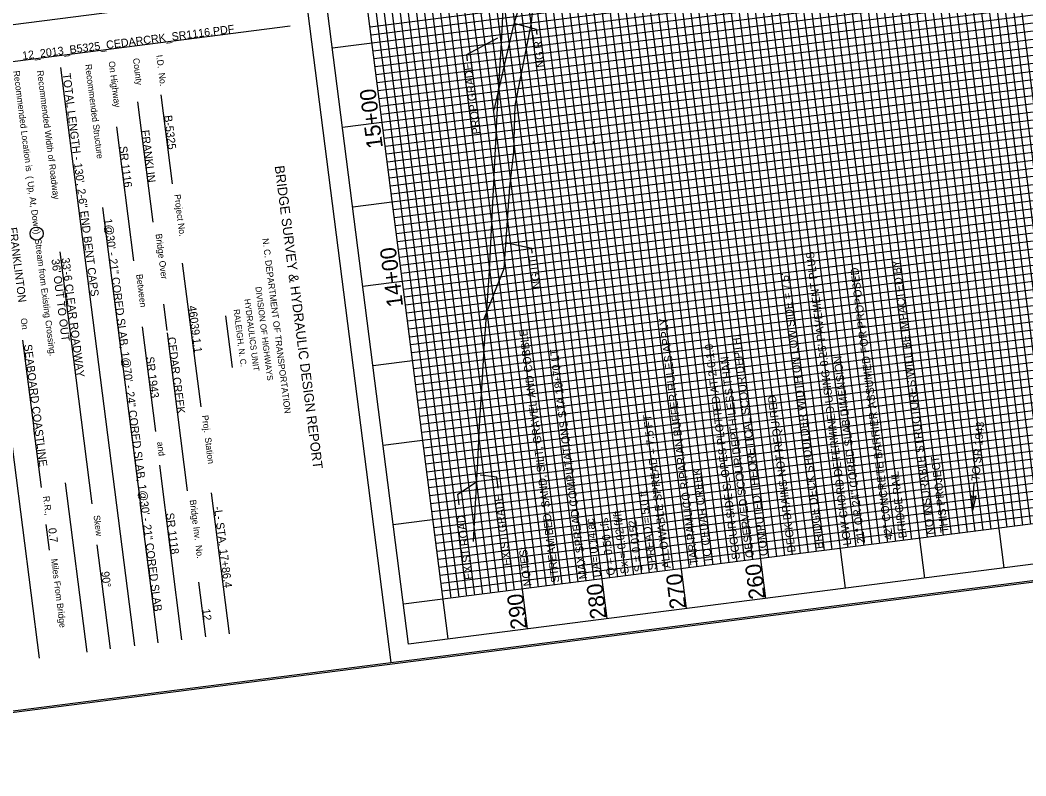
# Model space of a CAD drawing. Extents: x 2166991 to 2168413, y 842679 to 844296.
# Drawn here: x 2167468 to 2168096, y 842679 to 843150 of the extents above; entities that cross this region are included whole.
import ezdxf

# ---------------------------------------------------------------- set-up
doc = ezdxf.new("R2010")
doc.units = 0
for name, color, linetype in [('Exist Horizontal Alignment', 7, 'Continuous'), ('Exist Hydrographic Natural Ground Left', 7, 'Continuous'), ('Exist Hydrographic Natural Ground Right', 7, 'Continuous'), ('Old_Level_46', 7, 'Continuous'), ('Old_Level_61', 7, 'Continuous'), ('Prop Plan Preparation Cover Label', 7, 'Continuous'), ('Prop Plan Preparation Elevation Label', 7, 'Continuous'), ('Prop Plan Preparation Sheet Bridge Report Limited Study CELL', 7, 'Continuous'), ('Prop Plan Preparation Station Label', 7, 'Continuous'), ('Prop Plan Preparation Table Performance Curve CELL', 7, 'Continuous'), ('Scratch_Level_1', 7, 'Continuous'), ('Sheet Plot Border Outside CELL', 7, 'Continuous'), ('Typical Terminator CELL', 7, 'Continuous')]:
    doc.layers.add(name, color=color, linetype=linetype)

msp = doc.modelspace()

# ---------------------------------------------------------------- linework, layer by layer
at = {"layer": 'Exist Horizontal Alignment'}
msp.add_lwpolyline([(2167751.39, 842824.91), (2167752.39, 842844.74), (2167753.95, 842874.72), (2167755.15, 842897.27), (2167757.06, 842927.31), (2167757.92, 842945.41), (2167760.09, 842975.47), (2167761.25, 842993.97), (2167762.76, 843023.98), (2167763.76, 843044.55), (2167765.23, 843074.51), (2167766.29, 843095.78), (2167768.15, 843125.8), (2167769.02, 843139.96), (2167770.48, 843169.95), (2167771.39, 843188.46), (2167770.67, 843218.15), (2167770.25, 843236.07), (2167768.33, 843265.68), (2167767.02, 843285.86), (2167763.97, 843315.19), (2167760.56, 843343.94)], dxfattribs=at)
at = {"layer": 'Exist Hydrographic Natural Ground Left'}
msp.add_lwpolyline([(2167757.79, 842963.56), (2167770.55, 842995.45), (2167773.98, 843046.3), (2167776.61, 843068.3), (2167777.35, 843097.13), (2167787.62, 843148.85), (2167792.18, 843199.84), (2167793.61, 843214.01), (2167797.76, 843250.96), (2167815.06, 843303.58), (2167817.99, 843332.01), (2167815.17, 843366.59)], dxfattribs=at)
at = {"layer": 'Exist Hydrographic Natural Ground Right'}
msp.add_lwpolyline([(2167764.31, 843094.3), (2167776.57, 843147.44), (2167792.18, 843199.84), (2167810.26, 843216.13), (2167772.9, 843247.78)], dxfattribs=at)
at = {"layer": 'Old_Level_46'}
for points in [[(2167791.01, 843141.49), (2167790.62, 843144.55), (2167776.78, 843148.24)], [(2167747.61, 843125.02), (2167747.11, 843128.93), (2167766.47, 843139.45)], [(2167788.04, 843005.03), (2167787.67, 843007.92), (2167771.61, 843011.4)], [(2167742.33, 842847.83), (2167741.48, 842854.49), (2167753.3, 842862.19)], [(2167766.83, 842858.38), (2167765.98, 842865.05), (2167755.49, 842866.42)]]:
    msp.add_lwpolyline(points, dxfattribs=at)
at = {"layer": 'Old_Level_61'}
msp.add_line((2168062.86, 842844.16), (2168064.07, 842861.57), dxfattribs=at)
at = {"layer": 'Prop Plan Preparation Cover Label'}
msp.add_circle((2167478.55, 843017.15), 4.12, dxfattribs=at)
at = {"layer": 'Prop Plan Preparation Sheet Bridge Report Limited Study CELL'}
for p, q in [((2168132.34, 842814.84), (2167973.96, 844054.76)), ((2168082.74, 842808.5), (2167924.37, 844048.43)), ((2168033.15, 842802.17), (2167874.77, 844042.09)), ((2167983.55, 842795.83), (2167825.17, 844035.76)), ((2167933.95, 842789.5), (2167775.57, 844029.42)), ((2168124.21, 842839), (2167972.17, 844029.33)), ((2168134.13, 842840.27), (2167982.09, 844030.6)), ((2167884.35, 842783.16), (2167725.98, 844023.09)), ((2168074.61, 842832.67), (2167922.57, 844023)), ((2168084.53, 842833.93), (2167932.49, 844024.26)), ((2168089.49, 842834.57), (2167937.45, 844024.9)), ((2168094.45, 842835.2), (2167942.41, 844025.53)), ((2168099.41, 842835.83), (2167947.37, 844026.16)), ((2168104.37, 842836.47), (2167952.33, 844026.8)), ((2168109.33, 842837.1), (2167957.29, 844027.43)), ((2168114.29, 842837.73), (2167962.25, 844028.06)), ((2168119.25, 842838.37), (2167967.21, 844028.7)), ((2167834.76, 842776.83), (2167676.38, 844016.75)), ((2168025.02, 842826.33), (2167872.98, 844016.66)), ((2168034.94, 842827.6), (2167882.9, 844017.93)), ((2168039.9, 842828.23), (2167887.86, 844018.56)), ((2168044.86, 842828.87), (2167892.82, 844019.19)), ((2168049.82, 842829.5), (2167897.78, 844019.83)), ((2168054.78, 842830.13), (2167902.74, 844020.46)), ((2168059.74, 842830.77), (2167907.69, 844021.1)), ((2168064.7, 842831.4), (2167912.65, 844021.73)), ((2168069.66, 842832.03), (2167917.61, 844022.36)), ((2167538.09, 844014.21), (2167699.63, 842749.49)), ((2167538.09, 844014.21), (2167699.63, 842749.49)), ((2167785.16, 842770.49), (2167626.78, 844010.42)), ((2167985.34, 842821.26), (2167833.3, 844011.59)), ((2167990.3, 842821.9), (2167838.26, 844012.23)), ((2167995.26, 842822.53), (2167843.22, 844012.86)), ((2168000.22, 842823.16), (2167848.18, 844013.49)), ((2168005.18, 842823.8), (2167853.14, 844014.13)), ((2168010.14, 842824.43), (2167858.1, 844014.76)), ((2168015.1, 842825.06), (2167863.06, 844015.39)), ((2168020.06, 842825.7), (2167868.02, 844016.03)), ((2167935.74, 842814.93), (2167783.7, 844005.26)), ((2167940.7, 842815.56), (2167788.66, 844005.89)), ((2167945.66, 842816.2), (2167793.62, 844006.52)), ((2167950.62, 842816.83), (2167798.58, 844007.16)), ((2167955.58, 842817.46), (2167803.54, 844007.79)), ((2167960.54, 842818.1), (2167808.5, 844008.43)), ((2167965.5, 842818.73), (2167813.46, 844009.06)), ((2167970.46, 842819.36), (2167818.42, 844009.69)), ((2167975.42, 842820), (2167823.38, 844010.33)), ((2167710.76, 842760.99), (2167552.39, 844000.92)), ((2167735.56, 842764.16), (2167577.19, 844004.08)), ((2167886.15, 842808.59), (2167734.11, 843998.92)), ((2167891.11, 842809.23), (2167739.06, 843999.56)), ((2167896.07, 842809.86), (2167744.02, 844000.19)), ((2167901.03, 842810.49), (2167748.98, 844000.82)), ((2167905.98, 842811.13), (2167753.94, 844001.46)), ((2167910.94, 842811.76), (2167758.9, 844002.09)), ((2167915.9, 842812.39), (2167763.86, 844002.72)), ((2167920.86, 842813.03), (2167768.82, 844003.36)), ((2167925.82, 842813.66), (2167773.78, 844003.99)), ((2167836.55, 842802.26), (2167684.51, 843992.59)), ((2167841.51, 842802.89), (2167689.47, 843993.22)), ((2167846.47, 842803.53), (2167694.43, 843993.85)), ((2167851.43, 842804.16), (2167699.39, 843994.49)), ((2167856.39, 842804.79), (2167704.35, 843995.12)), ((2167861.35, 842805.43), (2167709.31, 843995.76)), ((2167866.31, 842806.06), (2167714.27, 843996.39)), ((2167871.27, 842806.69), (2167719.23, 843997.02)), ((2167876.23, 842807.33), (2167724.19, 843997.66)), ((2167786.95, 842795.92), (2167634.91, 843986.25)), ((2167791.91, 842796.56), (2167639.87, 843986.89)), ((2167796.87, 842797.19), (2167644.83, 843987.52)), ((2167801.83, 842797.82), (2167649.79, 843988.15)), ((2167806.79, 842798.46), (2167654.75, 843988.79)), ((2167811.75, 842799.09), (2167659.71, 843989.42)), ((2167816.71, 842799.72), (2167664.67, 843990.05)), ((2167821.67, 842800.36), (2167669.63, 843990.69)), ((2167826.63, 842800.99), (2167674.59, 843991.32)), ((2167737.35, 842789.59), (2167585.31, 843979.92)), ((2167742.31, 842790.22), (2167590.27, 843980.55)), ((2167747.27, 842790.86), (2167595.23, 843981.18)), ((2167752.23, 842791.49), (2167600.19, 843981.82)), ((2167757.19, 842792.12), (2167605.15, 843982.45)), ((2167762.15, 842792.76), (2167610.11, 843983.09)), ((2167767.11, 842793.39), (2167615.07, 843983.72)), ((2167772.07, 842794.02), (2167620.03, 843984.35)), ((2167777.03, 842794.66), (2167624.99, 843984.99)), ((2168182.75, 843209.4), (2167686.78, 843146.05)), ((2168183.39, 843204.44), (2167687.42, 843141.09)), ((2168184.02, 843199.48), (2167663.25, 843132.97)), ((2168184.65, 843194.53), (2167688.68, 843131.17)), ((2168185.29, 843189.57), (2167689.32, 843126.21)), ((2168185.92, 843184.61), (2167689.95, 843121.26)), ((2168186.55, 843179.65), (2167690.58, 843116.3)), ((2167100.22, 843101.38), (2167645.78, 843171.06)), ((2168187.19, 843174.69), (2167691.22, 843111.34)), ((2168187.82, 843169.73), (2167691.85, 843106.38)), ((2168188.45, 843164.77), (2167692.48, 843101.42)), ((2168189.09, 843159.81), (2167693.12, 843096.46)), ((2168189.72, 843154.85), (2167693.75, 843091.5)), ((2167458.71, 843124.09), (2167636.89, 843146.84)), ((2168190.36, 843149.89), (2167669.59, 843083.37)), ((2168190.99, 843144.93), (2167695.02, 843081.58)), ((2168191.62, 843139.97), (2167695.65, 843076.62)), ((2168192.26, 843135.01), (2167696.29, 843071.66)), ((2168192.89, 843130.05), (2167696.92, 843066.7)), ((2168193.52, 843125.09), (2167697.55, 843061.74)), ((2167493.43, 843120.82), (2167539.55, 842759.79)), ((2168194.16, 843120.13), (2167698.19, 843056.78)), ((2168194.79, 843115.17), (2167698.82, 843051.82)), ((2168195.42, 843110.21), (2167699.45, 843046.86)), ((2167556.1, 843103.79), (2167563.18, 843048.33)), ((2168196.69, 843100.29), (2167675.92, 843033.77)), ((2168196.06, 843105.25), (2167700.09, 843041.9)), ((2167541.52, 843099.51), (2167551.12, 843024.38)), ((2168197.32, 843095.33), (2167701.35, 843031.98)), ((2168197.96, 843090.37), (2167701.99, 843027.02)), ((2167528.4, 843083.87), (2167539.08, 843000.26)), ((2168198.59, 843085.41), (2167702.62, 843022.06)), ((2168199.22, 843080.45), (2167703.25, 843017.1)), ((2168199.86, 843075.49), (2167703.89, 843012.14)), ((2168200.49, 843070.53), (2167704.52, 843007.18)), ((2168201.13, 843065.57), (2167705.15, 843002.22)), ((2167440.83, 843059.14), (2167480.03, 842752.21)), ((2168201.76, 843060.61), (2167705.79, 842997.26)), ((2168203.03, 843050.69), (2167682.26, 842984.18)), ((2168202.39, 843055.65), (2167706.42, 842992.3)), ((2168203.66, 843045.73), (2167707.69, 842982.38)), ((2168204.29, 843040.77), (2167708.32, 842977.42)), ((2167519.71, 843033.5), (2167543.21, 842849.5)), ((2168204.93, 843035.81), (2167708.96, 842972.46)), ((2168205.56, 843030.85), (2167709.59, 842967.5)), ((2168206.19, 843025.9), (2167710.22, 842962.54)), ((2168206.83, 843020.94), (2167710.86, 842957.58)), ((2168207.46, 843015.98), (2167711.49, 842952.63)), ((2167493.01, 843005.77), (2167513.09, 842848.51)), ((2168208.09, 843011.02), (2167712.12, 842947.67)), ((2168208.73, 843006.06), (2167712.76, 842942.71)), ((2168209.36, 843001.1), (2167688.59, 842934.58)), ((2167569.51, 842998.77), (2167580.98, 842908.99)), ((2168209.99, 842996.14), (2167714.02, 842932.79)), ((2168210.63, 842991.18), (2167714.66, 842927.83)), ((2168211.26, 842986.22), (2167715.29, 842922.87)), ((2168211.89, 842981.26), (2167715.92, 842917.91)), ((2168212.53, 842976.3), (2167716.56, 842912.95)), ((2167557.66, 842973.2), (2167559.77, 842956.66)), ((2168213.16, 842971.34), (2167717.19, 842907.99)), ((2167596.41, 842965.95), (2167600.55, 842933.52)), ((2167596.41, 842965.95), (2167600.55, 842933.52)), ((2167596.41, 842965.95), (2167600.55, 842933.52)), ((2168213.8, 842966.38), (2167717.82, 842903.03)), ((2167544.34, 842959.06), (2167552.7, 842893.63)), ((2168214.43, 842961.42), (2167718.46, 842898.07)), ((2168215.06, 842956.46), (2167719.09, 842893.11)), ((2167469.79, 842950.77), (2167476.83, 842895.65)), ((2167559.96, 842955.2), (2167572.55, 842856.59)), ((2168215.7, 842951.5), (2167694.93, 842884.98)), ((2168216.33, 842946.54), (2167720.36, 842883.19)), ((2168216.96, 842941.58), (2167720.99, 842878.23)), ((2168217.6, 842936.62), (2167721.63, 842873.27)), ((2168218.23, 842931.66), (2167722.26, 842868.31)), ((2168218.86, 842926.7), (2167722.89, 842863.35)), ((2168219.5, 842921.74), (2167723.53, 842858.39)), ((2168220.13, 842916.78), (2167724.16, 842853.43)), ((2168220.76, 842911.82), (2167724.79, 842848.47)), ((2168221.4, 842906.86), (2167725.43, 842843.51)), ((2168222.03, 842901.9), (2167701.26, 842835.38)), ((2167481.55, 842858.68), (2167476.81, 842895.82)), ((2168222.66, 842896.94), (2167726.69, 842833.59)), ((2168223.3, 842891.98), (2167727.33, 842828.63)), ((2168223.93, 842887.02), (2167727.96, 842823.67)), ((2168224.56, 842882.06), (2167728.59, 842818.71)), ((2168225.2, 842877.1), (2167729.23, 842813.75)), ((2167569.31, 842763.59), (2167555.38, 842872.65)), ((2168225.83, 842872.14), (2167729.86, 842808.79)), ((2167496.3, 842861.59), (2167509.79, 842755.99)), ((2168226.47, 842867.18), (2167730.49, 842803.83)), ((2168227.1, 842862.22), (2167731.13, 842798.87)), ((2167599.07, 842767.39), (2167587.82, 842855.42)), ((2168227.73, 842857.27), (2167731.76, 842793.91)), ((2167554.43, 842761.69), (2167543.24, 842849.25)), ((2168228.37, 842852.31), (2167707.6, 842785.79)), ((2167486.56, 842819.5), (2167484.49, 842835.66)), ((2168231.53, 842827.51), (2167710.76, 842760.99)), ((2167524.67, 842757.89), (2167516.36, 842822.91)), ((2167584.19, 842765.5), (2167579.83, 842799.62))]:
    msp.add_line(p, q, dxfattribs=at)
msp.add_lwpolyline([(2166992.52, 843944.53), (2167154.06, 842679.8), (2168245.2, 842819.17), (2168083.66, 844083.9)], close=True, dxfattribs=at)
at = {"layer": 'Scratch_Level_1'}
msp.add_line((2167826.4, 843073.16), (2167826.21, 843074.63), dxfattribs=at)
at = {"layer": 'Sheet Plot Border Outside CELL'}
msp.add_lwpolyline([(2168246.32, 842818.31), (2168084.52, 844085.01), (2166991.4, 843945.39), (2167153.2, 842678.68)], close=True, dxfattribs=at)
at = {"layer": 'Typical Terminator CELL'}
msp.add_lwpolyline([(2168065.12, 842853.4), (2168062.86, 842844.16), (2168061.85, 842853.68), (2168063.43, 842852.37)], close=True, dxfattribs=at)

# ---------------------------------------------------------------- texts
at = {"layer": 'Old_Level_46'}
for s, p in [('NG RT ', (2167795.88, 843121.2)), ('PROP GRADE', (2167755.75, 843079.52)), ('NG LT', (2167793.31, 842983.17)), ('EXIST GRADE', (2167774.87, 842810.09)), ('EXIST ROAD', (2167750.94, 842801.47))]:
    msp.add_text(s, height=5, rotation=97.27898, dxfattribs=at).set_placement(p)
at = {"layer": 'Old_Level_61'}
msp.add_text('TO SR 1943', height=5, rotation=85.1501, dxfattribs=at).set_placement((2168067.18, 842862.53))
at = {"layer": 'Prop Plan Preparation Cover Label'}
for s, rotation, p in [('12_2013_B5325_CEDARCRK_SR1116.PDF', 7.27898, (2167469.86, 843125.75)), ('TOTAL LENGTH - 130\', 2-6" END BENT CAPS', 277.27898, (2167494.72, 843116.98)), ('B-5325', 277.27898, (2167558.08, 843090.79)), ('FRANKLIN', 277.27898, (2167543.77, 843081.56)), ('SR 1116', 277.27898, (2167530.03, 843071.5)), ('1@30\' - 21" CORED SLAB, 1@70\' - 24" CORED SLAB, 1@30\' - 21" CORED SLAB', 277.27898, (2167520.66, 843026.25)), ('FRANKLINTON', 277.27898, (2167461.25, 843020.77)), ("36' OUT TO OUT", 277.27898, (2167487.76, 843001.01)), ("33'-6 CLEAR ROADWAY ", 277.27898, (2167494.06, 843001.82)), ('46039.1.1', 277.27898, (2167573.26, 842971.95)), ('CEDAR CREEK', 277.27898, (2167560.28, 842952.33)), ('SEABOARD COASTLINE', 277.27898, (2167470.58, 842947.77)), ('SR 1943', 277.27898, (2167546.81, 842940.1)), ('SR 1118', 277.27898, (2167559.27, 842842.57)), ('-L- STA. 17+86.4', 277.27898, (2167589.27, 842846.55)), ('0.7', 277.27898, (2167485.75, 842833.17)), ('90%%d', 277.27898, (2167518.85, 842806.03)), ('12', 277.27898, (2167581.94, 842782.72))]:
    msp.add_text(s, height=5, rotation=rotation, dxfattribs=at).set_placement(p)
at = {"layer": 'Prop Plan Preparation Elevation Label'}
for s, p in [('260', (2167933.55, 842789.5)), ('270', (2167884.14, 842783.44)), ('280', (2167834.49, 842777.2)), ('290', (2167784.86, 842770.81))]:
    msp.add_text(s, height=10, rotation=97.27898, dxfattribs=at).set_placement(p)
at = {"layer": 'Prop Plan Preparation Sheet Bridge Report Limited Study CELL'}
for s, height, p in [('County', 4, (2167538.64, 843126.51)), ('I.D.  No.', 4, (2167553.24, 843128.53)), ('Recommended Location is  ( Up, At, Down)  Stream from Existing Crossing.', 4, (2167463.99, 843118.64)), ('Recommended Width of Roadway', 4, (2167478.73, 843118.81)), ('Recommended Structure', 4, (2167508.79, 843122.71)), ('On Highway', 4, (2167523.42, 843124.61)), ('BRIDGE SURVEY & HYDRAULIC DESIGN REPORT', 5.9999, (2167627.16, 843059.29)), ('Project No.', 4, (2167564.41, 843041.48)), ('Bridge Over', 4, (2167552.8, 843016.84)), ('N. C. DEPARTMENT OF TRANSPORTATION', 4, (2167619.46, 843014)), ('Between', 4, (2167540.67, 842991.63)), ('DIVISION OF HIGHWAYS', 3.7499, (2167615.1, 842983.86)), ('HYDRAULICS UNIT', 3.7499, (2167608.22, 842976.21)), ('RALEIGH, N. C.', 3.751, (2167601.46, 842969.76)), ('On', 4, (2167468.48, 842964.19)), ('Proj.  Station', 4, (2167581.72, 842903.61)), ('and', 4, (2167553.71, 842886.97)), ('R.R.,', 4, (2167482.51, 842853.12)), ('Bridge Inv.  No.', 4, (2167574.09, 842850.78)), ('Skew', 4, (2167514.08, 842841.15)), ('Miles From Bridge', 4, (2167487.51, 842813.98))]:
    msp.add_text(s, height=height, rotation=277.27898, dxfattribs=at).set_placement(p)
at = {"layer": 'Prop Plan Preparation Station Label'}
for s, p in [('15+00', (2167694.79, 843070.92)), ('14+00', (2167707.44, 842971.95))]:
    msp.add_text(s, height=10, rotation=97.27898, dxfattribs=at).set_placement(p)
at = {"layer": 'Prop Plan Preparation Table Performance Curve CELL'}
for s, p in [("LOW CHORD DETERMINED USING 0.25' PAVEMENT PLUS", (2167987.27, 842822.9)), ('NO INSURABLE STRUCTURES WILL BE IMPACTED BY ', (2168039.35, 842829.55)), ('42" CONCRETE BARRIER ASSUMED FOR PROPOSED ', (2168013.31, 842826.23)), ("BRIDGE DECK SHOULDER WIDTH ON LOW SIDE = 7.5'", (2167969.91, 842820.69)), ('TAR-PAMLICO RIPARIAN BUFFER RULES APPLY', (2167891.79, 842810.71)), ('STREAM BED: SAND, SILT, GRAVEL AND COBBLE', (2167805, 842799.62)), ('COMPUTED THEORETICAL SCOUR DEPTH.', (2167935.19, 842816.25)), ('MAX SPREAD COMPUTATIONS STA 18+70 LT', (2167822.36, 842801.84)), ('SCOUR SIDE SLOPES PLOTTED AT 2.0:1.0', (2167917.83, 842814.03)), ('OBSERVED SCOUR DEPTH LESS THAN ', (2167926.51, 842815.14)), ('21" OR 24" CORED SLAB DIMENSION', (2167995.95, 842824.01)), ('DECK DRAINS NOT REQUIRED', (2167952.55, 842818.47)), ('ALLOWABLE SPREAD = 7.5 FT', (2167874.44, 842808.49)), ('THIS PROJECT', (2168048.02, 842830.66)), ('TO CEDAR CREEK', (2167900.47, 842811.82)), ('BRIDGE RAIL', (2168021.99, 842827.34)), ('SPREAD = 5.0 ft', (2167865.76, 842807.38)), ('Sx = 0.02 ft/ft', (2167848.4, 842805.16)), ('DA= 0.14 ac', (2167831.04, 842802.95)), ('Q = 0.50 cfs', (2167839.72, 842804.06)), ('S = 0.0152', (2167857.08, 842806.27)), ('NOTES:', (2167787.64, 842797.4))]:
    msp.add_text(s, height=5, rotation=97.27898, dxfattribs=at).set_placement(p)

doc.saveas('drawing.dxf')
